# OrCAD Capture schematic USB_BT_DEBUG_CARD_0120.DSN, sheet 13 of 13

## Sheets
13 PAGE11 P5V to P3V3/ Super cap: size A3
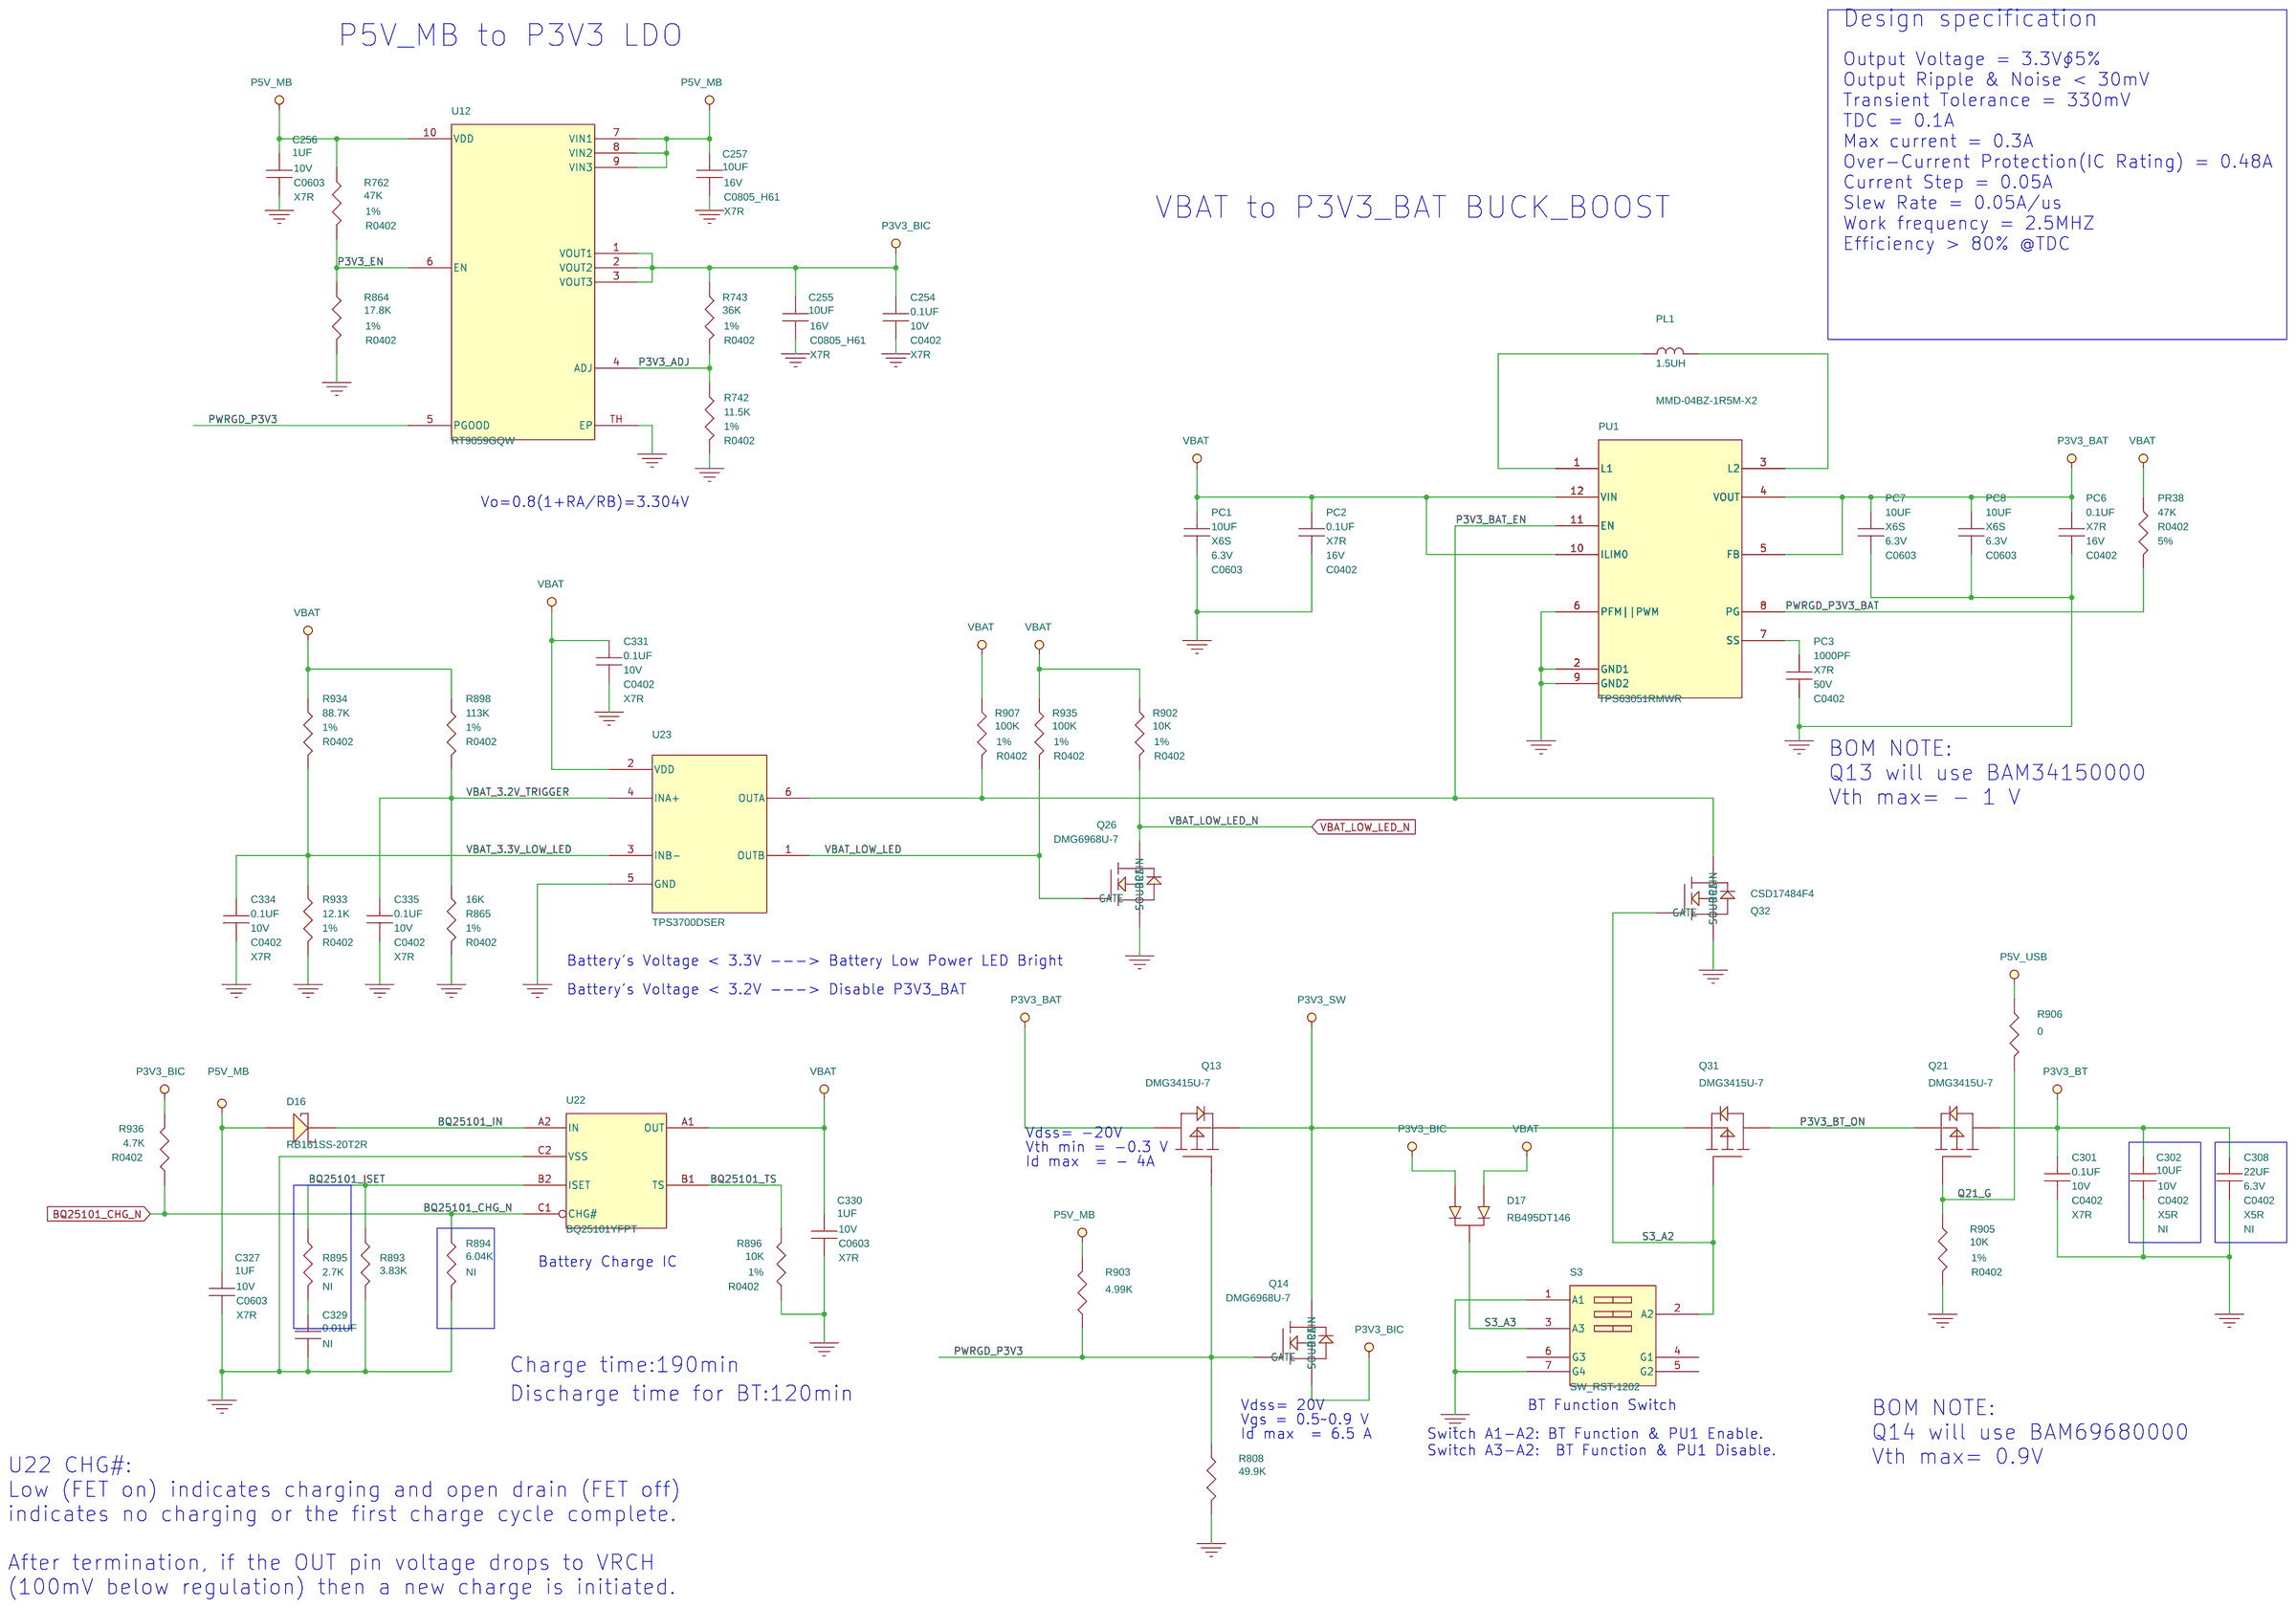
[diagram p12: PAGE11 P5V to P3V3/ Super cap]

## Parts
C254  0.1UF  [C0402]
C255  10UF  [C0805_H61]
C256  1UF  [C0603]
C257  10UF  [C0805_H61]
C301  0.1UF  [C0402]
C302  10UF  [C0402]
C308  22UF  [C0402]
C327  1UF  [C0603]
C329  0.01UF  [C0402]
C330  1UF  [C0603]
C331  0.1UF  [C0402]
C334  0.1UF  [C0402]
C335  0.1UF  [C0402]
D16  RB161SS-20T2R  [D0603_RB161SS-20T2R]
D17  RB495DT146  [SOT346_0-95_2-9X1-6]
PC1  10UF  [C0603]
PC2  0.1UF  [C0402]
PC3  1000PF  [C0402]
PC6  0.1UF  [C0402]
PC7  10UF  [C0603]
PC8  10UF  [C0603]
PL1  1.5UH  [L_MMD-04BZ-1R5M-X2]
PR38  47K  [R0402]
PU1  TPS63051RMWR  [VQFN12_0-5_2-5X2-5]
Q13  DMG3415U-7  [SOT23_GDSXC]
Q14  DMG6968U-7  [SOT23_GDSXC]
Q21  DMG3415U-7  [SOT23_GDSXC]
Q26  DMG6968U-7  [SOT23_GDSXC]
Q31  DMG3415U-7  [SOT23_GDSXC]
Q32  CSD17484F4  [PICOSTAR_GDS]
R742  11.5K  [R0402]
R743  36K  [R0402]
R762  47K  [R0402]
R808  49.9K  [R0402]
R864  17.8K  [R0402]
R865  16K  [R0402]
R893  3.83K  [R0402]
R894  6.04K  [R0402]
R895  2.7K  [R0402]
R896  10K  [R0402]
R898  113K  [R0402]
R902  10K  [R0402]
R903  4.99K  [R0402]
R905  10K  [R0402]
R906  0  [R0402]
R907  100K  [R0402]
R933  12.1K  [R0402]
R934  88.7K  [R0402]
R935  100K  [R0402]
R936  4.7K  [R0402]
S3  SW_RST-1202  [SW_RST-1202]
U12  RT9059GQW  [DFN10_THXE]
U22  BQ25101YFPT  [DSBGA6_0-4_0-88X1-58]
U23  TPS3700DSER  [WSON6_0-5_1-5X1-5]

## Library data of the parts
C254 C331 = CAP_NP: CAP CHIP 0.1U 10V(+-5%.X7R.0402); CLASS: DISCRETE; CMPLS_LVL: PF(V1)_Tmp; Data: WTC_LF_CAP SERIES-3.pdf; From_pj: TU2-ANNIE; Lifecycle: Comp-Approve; MATERIAL: X7R; Manuf_PN: 0402B104J100CT; Manuf_name: WALSIN TECHNOLOGY CORPORATION; Manuftr: WTC; Part_Type: *LF_C0402; Standard: ##; TOLERANCE: 5%; TOP_BOT: TOP; VOLTAGE: 10V; fp_ECN: 0402 SERIES_LL34.xls
C255 C257 = CAP_NP: CAP CHIP 10UF 16V(+-10%,X7R,0805); CLASS: DISCRETE; CMPLS_LVL: EP(V1); Data: SAM_MLCC SERIES_20130308.pdf; From_pj: T2H-CHEESE; Lifecycle: Comp-Approve; MATERIAL: X7R; Manuf_PN: CL21B106KOQNNNE; Manuf_name: SAMSUNG ELECTRONICS CO.,LTD; Manuftr: SAM; Part_Type: *LF_C0805; RD_CMPLS_LVL: EP(V1); TOLERANCE: 10%; TOP_BOT: TOP; VOLTAGE: 16V
C256 C327 C330 = CAP_NP: CAP CHIP 1U 10V(+-10%.X7R.0603); CLASS: DISCRETE; CMPLS_LVL: EP; Data: WTC_CAPACITOR SERIES.pdf; From_pj: T94-JEFF; Lifecycle: Comp-Approve; MATERIAL: X7R; Manuf_PN: 0603B105K100CT; Manuf_name: WALSIN TECHNOLOGY CORPORATION; Manuftr: WTC; Part_Type: *LF_C0603; Standard: ##; TOLERANCE: 10%; TOP_BOT: TOP; VOLTAGE: 10V
C301 C334 C335 = CAP_NP: CAP CHIP 0.1U 10V(+-5%.X7R.0402); CLASS: DISCRETE; CMPLS_LVL: PF(V1)_Tmp; Data: WTC_LF_CAP SERIES-3.pdf; From_pj: TU2-ANNIE; Lifecycle: Comp-Approve; MATERIAL: X7R; Manuf_PN: 0402B104J100CT; Manuf_name: WALSIN TECHNOLOGY CORPORATION; Manuftr: WTC; Part_Type: *LF_C0402; Standard: ##; TOLERANCE: 5%; TOP_BOT: BOT; VOLTAGE: 10V; fp_ECN: 0402 SERIES_LL34.xls
C302 = CAP_NP: CAP CHIP 10U 10V (+-20%, X5R, 0402); CLASS: DISCRETE; Data: CL05A106MP5NUNC.pdf; From_pj: T6VA-RAYMOND; Lifecycle: Comp-Approve; MATERIAL: X5R; Manuf_PN: CL05A106MP5NUNC; Manuf_name: SAMSUNG ELECTRONICS CO.,LTD (Samsung Mobile Display) / SAMSUNG SDI CO.,LTD; Manuftr: SAM; Not_insert: NI; Part_Type: *LF_C0402; RD_CMPLS_LVL: EP(V1); TOLERANCE: 20%; TOP_BOT: BOT; VOLTAGE: 10V; fp_ECN: 0402 SERIES_LL34.xls
C308 = CAP_NP: CAP CHIP 22U 6.3V(+-20%,X5R,0402); CLASS: DISCRETE; CMPLS_LVL: EP(V1); From_pj: T7A-JOSEPH; Lifecycle: Comp-Release Qty; MATERIAL: X5R; Manuf_PN: GRM155R60J226M; Manuf_name: MURATA ERIE N.A. INC TAIWAN BRANCH Okayama Murata Mfg.Co.,Ltd.Wakura Murata Mfg. Co., Ltd.; Manuftr: MUR; Not_insert: NI; Part_Category: Non-Consign; Part_Type: *LF_C0402; RD_CMPLS_LVL: EP(V1); TOLERANCE: 20%; TOP_BOT: BOT; VOLTAGE: 6.3V; fp_ECN: 0402 SERIES_LL34.xls
C329 = CAP_NP: CAP CHIP 0.01U 25V (+-5%,X7R,0402); CLASS: DISCRETE; CMPLS_LVL: EP(V1); Data: MUR_GRM155R71E103J.pdf; From_pj: T2H-WADE; Lifecycle: Comp-Approve; MATERIAL: X7R; Manuf_PN: GRM155R71E103J; Manuf_name: MURATA ERIE N.A. INC TAIWAN BRANCH Okayama Murata Mfg.Co.,; Manuftr: MUR; Not_insert: NI; Part_Type: *LF_C0402; RD_CMPLS_LVL: EP(V1); TOLERANCE: 5%; TOP_BOT: BOT; VOLTAGE: 25V; fp_ECN: 0402 SERIES_LL34.xls
D16 = MBRS340_0: DIODE SMD RB161SS-20T2R(30V,1A)SCHOTTKY; CLASS: IC; Data: ROH_RB161SS-20T2R.pdf; From_pj: F06-SHERRY; Lifecycle: Comp-Release Qty; MATERIAL: IC; Manuf_name: ROHM CO.,LTD.; Manuftr: ROH; Part_Type: *LF_Semiconductor; RD_CMPLS_LVL: EP(V1); TOP_BOT: TOP
D17 = RB495DT146: DIODE SMD RB495DT146(40V,0.4A); CLASS: IC; CMPLS_LVL: EU(V1); Data: ROH_RB495DT146.pdf; ESD_CDM: NA; ESD_HBM: NA; ESD_MM: NA; From_pj: S5H-HARRY; Lifecycle: Comp-Approve; MATERIAL: IC; MSD: NA; Manuf_name: ROHM CO.,LTD.; Manuftr: ROH; PIN_LENGTH_LONG_PIN: 0 MILS; PIN_LENGTH_SHORT_PIN: 0 MILS; Part_Type: *LF_Semiconductor; RD_CMPLS_LVL: EU(V1)
PC1 PC7 PC8 = CAP_NP: CAP CHIP 10U 6.3V(+-20%,X6S,0603); CLASS: DISCRETE; CMPLS_LVL: EP(V1); Data: MUR_JEMCG-4187DZ_20131126.pdf; From_pj: F06-RAYMOND; Lifecycle: Comp-Approve; MATERIAL: X6S; Manuf_PN: GRM188C80J106M; Manuf_name: MURATA ERIE N.A. INC TAIWAN BRANCH Okayama Murata Mfg.Co.,; Manufacturer: MAT; Manuftr: MUR; Part_Type: *LF_C0603; RD_CMPLS_LVL: EP(V1); TOLERANCE: 20%; TOP_BOT: TOP; VOLTAGE: 6.3V
PC2 PC6 = CAP_NP: CAP CHIP 0.1U 16V(10%.X7R.0402); CLASS: DISCRETE; CMPLS_LVL: EP; Data: MUR_LF_CAP SERIES_1.pdf; From_pj: S10-ANTONY; MATERIAL: X7R; Manuf_PN: GRM155R71C104K; Manuf_name: MURATA ERIE N.A. INC TAIWAN BRANCH Okayama Murata Mfg.Co..Ltd. Wakura Murata Mfg; Manufacturer: TAY; Manuftr: MUR; Part_Type: *LF_C0402; Standard: ##; Status: Preferred; TOLERANCE: 10%; TOP_BOT: TOP; VOLTAGE: 16V
PC3 = CAP_NP: CAP CHIP 1000P 50V(+-5%.X7R.0402); CLASS: DISCRETE; CMPLS_LVL: EP; Data: RHT_LF_CAP SERIES-2.pdf; From_pj: A05-DEMON; MATERIAL: X7R; Manuf_PN: C1005X7R102JGT; Manuf_name: ACER PERIPHERALS INC.(Darfon Electronics Corp.); Manufacturer: TAY; Manuftr: API; Part_Type: *LF_C0402; Status: Preferred; TOLERANCE: 5%; TOP_BOT: TOP; VOLTAGE: 50V; fp_ECN: 0402 SERIES_LL34.xls
PL1 = L: IND SMD 1.5UH 20% 4A MMD-04BZ-1R5M-X2; CLASS: DISCRETE; CMPLS_LVL: EP(V1); Current_Amp: 4A; Data: MAG_MMD-04BZ-1R5M-X2.pdf; From_pj: S2B-KC; Lifecycle: Comp-Approve; MATERIAL: IND; Manuf_PN: MMD-04BZ-1R5M-X2; Manuf_name: MAG. LAYERS (MAG.LAYERS Scientific-Technics Co., Ltd); Manuftr: MAG; Part_Type: *LF_Inductor; RD_CMPLS_LVL: EP(V1); TOP_BOT: TOP; fp_ECN: L_MMD-04BZ-1R5M-X2.msg
PR38 = R: RES CHIP 47K 1/16W +-5% (0402); CLASS: DISCRETE; CMPLS_LVL: EP; Data: WTC_LF_WR SERIES-4.pdf; From_pj: S93-MARTIN; Lifecycle: Comp-Approve; MATERIAL: CHIP; Manuf_PN: WR04X473 JTL; Manuf_name: WALSIN TECHNOLOGY CORPORATION; Manufacturer: CYN; Manuftr: WTC; Part_Type: *LF_Resistor; TOLERANCE: 5%; TOP_BOT: TOP; WATTAGE: 1/16W; fp_ECN: 0402 SERIES_LL34.xls
PU1 = TPS63051RMWR: IC OTHER(12P)TPS63051RMWR(VQFN-HR); CLASS: IC; Data: TIC_TPS63051RMWR_revJULY-2015.pdf; From_pj: F08-ANSON; Lifecycle: P/N Release; MATERIAL: IC; Manuf_name: TEXAS INSTRUMENTS SUPPLY CO.,; Manuftr: TIC; Part_Type: *LF_Chipset; RD_CMPLS_LVL: EP(V1); Standard: Potential; TOP_BOT: TOP
Q13 Q21 Q31 = MOSFET_PCH_GDS: TRANS MOS DMG3415U-7(-20V,-4A,0.9W)SOT23; CLASS: IC; CMPLS_LVL: EP(V1); Data: DDS_DMG3415U_REV3-2.pdf; From_pj: S1N-AI-JU; Lifecycle: Comp-Approve; MATERIAL: IC; Manuf_name: DIODES TAIWAN CO.,LTD.(Kai Hong Shanghai); Manuftr: DDS; Part_Type: *LF_Semiconductor; TOP_BOT: TOP
Q14 Q26 = MOSFET_N_GSD: TRANS MOS DMG6968U-7(20V,6.5A,1.3W)SOT23; CLASS: IC; Data: DDS_DMG6968U.pdf; From_pj: S1N-AI-JU; Lifecycle: Comp-Approve; MATERIAL: IC; Manuf_name: DIODES TAIWAN CO.,LTD.(Kai Hong Shanghai); Manuftr: DDS; Part_Type: *LF_Semiconductor; RD_CMPLS_LVL: EP(V1); TOP_BOT: TOP
Q32 = MOSFET_N_GSD: TRANS MOS CSD17484F4(30V,3A,0.5W); CLASS: IC; Data: TIC_CSD17484F4.pdf; ESD_CDM: NA; ESD_HBM: NA; ESD_MM: NA; From_pj: F08-TOM; Lifecycle: P/N Release; MATERIAL: IC; MSD: NA; Manuf_name: TEXAS INSTRUMENTS SUPPLY CO.,; Manuftr: TIC; PIN_LENGTH_LONG_PIN: 0 MILS; PIN_LENGTH_SHORT_PIN: 0 MILS; Part_Type: *LF_Semiconductor; RD_CMPLS_LVL: EP(V1); Standard: Potential; TOP_BOT: BOT
R742 = R: RES CHIP 11.5K 1/16W +-1%( 0402); CLASS: DISCRETE; CMPLS_LVL: EP; Data: MAT_LF_RES SERIES.pdf; From_pj: LSI-KC; Lifecycle: Comp-Approve; MATERIAL: CHIP; Manuf_PN: ERJ2RKF1152X; Manuf_name: MATSUSHITA ELECTRONICS CORPORATION (PANASONIC)Wuxi Matsushita Battery Co.. Ltd; Manuftr: MAT; Part_Type: *LF_Resistor; TOLERANCE: 1%; TOP_BOT: TOP; WATTAGE: 1/16W; fp_ECN: 0402 SERIES_LL34.xls
R743 = R: RES CHIP 36K 1/16W +-1%(0402); CLASS: DISCRETE; CMPLS_LVL: EP; Data: RHT_LF_RES SERIES-2.pdf; From_pj: LB6-JAMES; MATERIAL: CHIP; Manuf_PN: CR0236K0F002S; Manuf_name: RTECH TECHNOLOGY CO..LTD. (Compostar); Manuftr: RHT; Part_Type: *LF_Resistor; TOLERANCE: 1%; TOP_BOT: TOP; WATTAGE: 1/16W; fp_ECN: 0402 SERIES_LL34.xls
R762 = R: RES CHIP 47K 1/16W +-1% (0402); CLASS: DISCRETE; CMPLS_LVL: EP; Data: RHT_LF_RES SERIES-2.pdf; From_pj: T96-KC; Lifecycle: Comp-Release Qty; MATERIAL: CHIP; Manuf_PN: CR0247K0F002S; Manuf_name: RTECH TECHNOLOGY CO..LTD.(Compostar); Manuftr: RHT; Part_Type: *LF_Resistor; Standard: ##; TOLERANCE: 1%; TOP_BOT: TOP; WATTAGE: 1/16W; fp_ECN: 0402 SERIES_LL34.xls
R808 = R: RES CHIP 49.9K 1/16W +-1%(0402); CLASS: DISCRETE; CMPLS_LVL: EP; Data: WTC_LF_WR SERIES-4.pdf; From_pj: LU1-EASON; Lifecycle: Comp-Approve; MATERIAL: CHIP; Manuf_PN: WR04X4992FTL; Manuf_name: WALSIN TECHNOLOGY CORPORATION; Manuftr: WTC; Part_Type: *LF_Resistor; Standard: ##; TOLERANCE: 1%; TOP_BOT: TOP; WATTAGE: 1/16W; fp_ECN: 0402 SERIES_LL34.xls
R864 = R: RES CHIP 17.8K 1/16W +- 1% (0402); CLASS: DISCRETE; CMPLS_LVL: EP; Data: WTC_LF_WR SERIES-4.pdf; From_pj: T96-KC; Lifecycle: Comp-Approve; MATERIAL: CHIP; Manuf_PN: WR04X1782FTL; Manuf_name: WALSIN TECHNOLOGY CORPORATION; Manuftr: WTC; Part_Type: *LF_Resistor; Standard: ##; TOLERANCE: 1%; TOP_BOT: TOP; WATTAGE: 1/16W; fp_ECN: 0402 SERIES_LL34.xls
R865 = R: RES CHIP 16K 1/16W +-1%(0402); CLASS: DISCRETE; CMPLS_LVL: EP; Data: YGO_RC SERIES_1.pdf; From_pj: TU1-RICHARD; MATERIAL: CHIP; Manuf_PN: RC0402FR-0716KL; Manuf_name: YAGEO CORPORATION; Manuftr: YGO; Part_Type: *LF_Resistor; TOLERANCE: 1%; TOP_BOT: TOP; WATTAGE: 1/16W; fp_ECN: 0402 SERIES_LL34.xls
R893 = R: RES CHIP 3.83K 1/16W +-1%(0402); CLASS: DISCRETE; CMPLS_LVL: EP(V1); Data: WTC_LF_WR SERIES-5.pdf; From_pj: S81K-KEN; Lifecycle: Comp-Approve; MATERIAL: CHIP; Manuf_PN: WR04X3831FTL; Manuf_name: WALSIN TECHNOLOGY CORPORATION; Manuftr: WTC; Part_Type: *LF_Resistor; RD_CMPLS_LVL: EP(V1); TOLERANCE: 1%; TOP_BOT: BOT; WATTAGE: 1/16W; fp_ECN: 0402 SERIES_LL34.xls
R894 = R: RES CHIP 6.04K 1/16W +-1%(0402); CLASS: DISCRETE; CMPLS_LVL: EP; Data: YGO_RC0201.pdf; From_pj: YK1-KEVIN; Lifecycle: Comp-Approve; MATERIAL: CHIP; Manuf_PN: RC0402FR-076K04; Manuf_name: YAGEO CORPORATION; Manuftr: YGO; Not_insert: NI; Part_Type: *LF_Resistor; Standard: ##; TOLERANCE: 1%; TOP_BOT: BOT; WATTAGE: 1/16W; fp_ECN: 0402 SERIES_LL34.xls
R895 = R: RES CHIP 2.7K 1/16W +-1%(0402); CLASS: DISCRETE; CMPLS_LVL: EP; Data: RHT_LF_RES SERIES-2.pdf; From_pj: S93-MARTIN; Lifecycle: Comp-Approve; MATERIAL: CHIP; Manuf_PN: CR022K70F002S; Manuf_name: RTECH TECHNOLOGY CO..LTD. (Compostar); Manuftr: RHT; Not_insert: NI; Part_Type: *LF_Resistor; TOLERANCE: 1%; TOP_BOT: BOT; WATTAGE: 1/16W; fp_ECN: 0402 SERIES_LL34.xls
R896 R902 R905 = R: RES CHIP 10K 1/16W +-1% (0402); CLASS: DISCRETE; CMPLS_LVL: EP; Data: WTC_LF_WR SERIES.pdf; From_pj: S82; Lifecycle: Comp-Approve; MATERIAL: CHIP; Manuf_PN: RR0510S-103-FN; Manuf_name: CYNTEC CO.. LTD.; Manuftr: CYN; Part_Type: *LF_Resistor; Status: Preferred; TOLERANCE: 1%; TOP_BOT: TOP; WATTAGE: 1/16W; fp_ECN: 0402 SERIES_LL34.xls
R898 = R: RES CHIP 113K 1/16W +-1%(0402); CLASS: DISCRETE; CMPLS_LVL: EP(V1); From_pj: T6MQ-TERRY; Lifecycle: Comp-Release Qty; MATERIAL: CHIP; Manuf_PN: RR0510S-1133-FN; Manuf_name: CYNTEC CO., LTD.; Manuftr: CYN; Part_Type: *LF_Resistor; RD_CMPLS_LVL: EP(V1); TOLERANCE: 1%; TOP_BOT: TOP; WATTAGE: 1/16W; fp_ECN: 0402 SERIES_LL34.xls
R903 = R: RES CHIP 4.99K 1/16W +-1% (0402); CLASS: DISCRETE; Data: YAGEO_RC.pdf; From_pj: S82-ICE; MATERIAL: CHIP; Manuf_PN: RC0402FR-074K99; Manuf_name: YAGEO CORPORATION; Manuftr: YGO; Part_Type: Resistor; Status: Normal; TOLERANCE: 1%; TOP_BOT: TOP; WATTAGE: 1/16W; fp_ECN: 0402 SERIES_LL34.xls
R906 = R: RESISTOR CHIP 0 1/16W +-5%(0402); CLASS: DISCRETE; CMPLS_LVL: EP; Data: WTC_LF_WR SERIES.pdf; Lifecycle: Comp-Approve; MATERIAL: CHIP; Manuf_PN: RR0510X-000-XN; Manuf_name: CYNTEC CO.. LTD.; Manuftr: CYN; Part_Type: *LF_Resistor; Status: Preferred; TOLERANCE: 5%; TOP_BOT: BOT; WATTAGE: 1/16W; fp_ECN: 0402 SERIES_LL34.xls
R907 R935 = R: RES CHIP 100K 1/16W +-1%(0402)EF; CLASS: DISCRETE; From_pj: S6E-KENHU; Lifecycle: Comp-Approve; MATERIAL: CHIP; Manuf_PN: WR04X1003FTR; Manuf_name: WALSIN TECHNOLOGY CORPORATION; Manuftr: WTC; Part_Type: *LF_Resistor; RD_CMPLS_LVL: EP(V1); Standard: End of Design; TOLERANCE: 1%; TOP_BOT: TOP; WATTAGE: 1/16W; fp_ECN: 0402 SERIES_LL34.xls
R933 = R: RES CHIP 12.1K 1/16W +-1%(0402); CLASS: DISCRETE; CMPLS_LVL: EP; Data: WTC_LF_WR SERIES-4.pdf; From_pj: T96-KC; MATERIAL: CHIP; Manuf_PN: WR04X1212FTL; Manuf_name: WALSIN TECHNOLOGY CORPORATION; Manuftr: WTC; Part_Type: *LF_Resistor; TOLERANCE: 1%; TOP_BOT: BOT; WATTAGE: 1/16W; fp_ECN: 0402 SERIES_LL34.xls
R934 = R: RES CHIP 88.7K 1/16W +-1%(0402); CLASS: DISCRETE; Data: YGO_RC SERIES_1.pdf; From_pj: LB9-ERIC; Lifecycle: Comp-Approve; MATERIAL: CHIP; Manuf_PN: RC0402FR-0788K7L; Manuf_name: YAGEO CORPORATION; Manuftr: YGO; Part_Type: *LF_Resistor; RD_CMPLS_LVL: EP(V1); TOLERANCE: 1%; TOP_BOT: BOT; WATTAGE: 1/16W; fp_ECN: 0402 SERIES_LL34.xls
R936 = R: RES CHIP 4.7K 1/16W +-5% (0402); CLASS: DISCRETE; CMPLS_LVL: EP; Data: WTC_LF_WR SERIES.pdf; Lifecycle: Comp-Approve; MATERIAL: CHIP; Manuf_PN: RR0510S-472-JN; Manuf_name: CYNTEC CO.. LTD.; Manuftr: CYN; Part_Type: *LF_Resistor; Status: Preferred; TOLERANCE: 5%; TOP_BOT: BOT; WATTAGE: 1/16W; fp_ECN: 0402 SERIES_LL34.xls
S3 = RST-1202: SWITCH SLIDE SMD 3P RST-1202; CLASS: IO; CMPLS_LVL: EP(V1)_Tmp; Data: RST-1202.pdf; From_pj: LU1-EASON; Lifecycle: Comp-Approve; MATERIAL: MECH; Manuf_name: TOKAI SANGYO CO..LTD; Manuftr: TKS; Part_Type: *LF_Mech; Standard: Non-Preferred; TOP_BOT: TOP
U12 = RT9059GQW: IC OTHER(10P) RT9059GQW(WDFN); CLASS: IC; Data: RTK_RT9059_rev2012.pdf; From_pj: S4E-ALAN; Lifecycle: Comp-Approve; MATERIAL: IC; Manuf_name: RICHTEK TECHNOLOGY CORPORATION; Manuftr: RTK; Part_Type: *LF_Chipset; RD_CMPLS_LVL: EP(V1); TOP_BOT: TOP
U22 = BQ25101YFPT: IC CTRL(6P)BQ25101YFPT(DSBGA); CLASS: IC; CMPLS_LVL: EU(V1); Data: TIC_BQ25101YFPT.pdf; From_pj: F08-MIKE; Lifecycle: P/N Release; MATERIAL: IC; Manuf_name: TEXAS INSTRUMENTS SUPPLY CO.,; Manuftr: TIC; Part_Type: *LF_Chipset; RD_CMPLS_LVL: EU(V1); Standard: Potential; TOP_BOT: TOP
U23 = TPS3700DSER: IC OTHER(6P)TPS3700DSER(WSON); CLASS: IC; Data: TIC_TPS3700.pdf; From_pj: T2H-GAVEN; Lifecycle: Comp-Approve; MATERIAL: IC; Manuf_name: TEXAS INSTRUMENTS SUPPLY CO.,; Manuftr: TIC; Part_Type: *LF_Chipset; RD_CMPLS_LVL: EP(V1); Standard: Potential; TOP_BOT: TOP

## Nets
GND: C254.2 C255.2 C256.2 C257.2 C301.2 C302.2 C308.2 C327.2 C329.2 C330.2 C331.2 C334.2 C335.2 PC1.2 PC2.2 PC3.2 PC6.2 PC7.2 PC8.2 PU1.2(GND1) PU1.6(PFM||PWM) PU1.9(GND2) Q26.S(SOURCE) Q32.S(SOURCE) R742.2 R808.2 R864.2 R865.2 R893.2 R894.2 R896.2 R905.2 R933.2 S3.1(A1) S3.7(G4) U12.TH(EP) U22.C2(VSS) U23.5(GND) ; also on sheet 7 8 9 10 12
P3V3_ADJ: R742.1 R743.2 U12.4(ADJ)
P3V3_BAT: PC6.1 PC7.1 PC8.1 PU1.4(VOUT) PU1.5(FB) Q13.D
P3V3_BAT_EN: PU1.11(EN) Q32.D(DRAIN) R907.2 U23.6(OUTA)
P3V3_BIC: C254.1 C255.1 D17.2 Q14.S(SOURCE) R743.1 R936.1 U12.1(VOUT1) U12.2(VOUT2) U12.3(VOUT3) ; also on sheet 7 8 9 10 12
P3V3_BT: C301.1 C302.1 C308.1 Q21.D ; also on sheet 12
P3V3_BT_ON: Q21.S Q31.D
P3V3_EN: R762.2 R864.1 U12.6(EN)
P3V3_SW: Q13.S Q14.D(DRAIN) Q31.S ; also on sheet 12
P5V_MB: C256.1 C257.1 C327.1 D16.A R762.1 R903.2 U12.7(VIN1) U12.8(VIN2) U12.9(VIN3) U12.10(VDD) ; also on sheet 7 8 9 12
P5V_USB: R906.2 ; also on sheet 12
VBAT: C330.1 C331.1 D17.1 PC1.1 PC2.1 PR38.1 PU1.10(ILIM0) PU1.12(VIN) R898.1 R902.1 R907.1 R934.1 R935.1 U22.A1(OUT) U23.2(VDD) ; also on sheet 8 9
VBAT_3.2V_TRIGGER: C335.1 R865.1 R898.2 U23.4(INA+)
VBAT_3.3V_LOW_LED: C334.1 R933.1 R934.2 U23.3(INB-)
VBAT_LOW_LED: Q26.G(GATE) R935.2 U23.1(OUTB)
VBAT_LOW_LED_N: Q26.D(DRAIN) R902.2 ; also on sheet 9
BQ25101_CHG_N: R894.1 R936.2 U22.C1(CHG#) ; also on sheet 9
BQ25101_IN: D16.C U22.A2(IN)
BQ25101_ISET: R893.1 R895.1 U22.B2(ISET)
BQ25101_TS: R896.1 U22.B1(TS)
G1: S3.4(G1)
G2: S3.5(G2)
G3: S3.6(G3)
PWRGD_P3V3: Q13.G Q14.G(GATE) R808.1 R903.1 U12.5(PGOOD)
PWRGD_P3V3_BAT: PR38.2 PU1.8(PG)
Q21_G: Q21.G R905.1 R906.1
S3_A2: Q31.G Q32.G(GATE) S3.2(A2)
S3_A3: D17.3 S3.3(A3)
N18364020: PL1.1 PU1.1(L1)
N18364026: PL1.2 PU1.3(L2)
N18364174: PC3.1 PU1.7(SS)
N18393594: C329.1 R895.2

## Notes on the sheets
sheet 13
- Design specification
- P5V_MB to P3V3 LDO
- Output Voltage = 3.3V∮5%
  Output Ripple & Noise < 30mV
  Transient Tolerance = 330mV
  TDC = 0.1A
  Max current = 0.3A
  Over-Current Protection(IC Rating) = 0.48A
  Current Step = 0.05A
  Slew Rate = 0.05A/us
  Work frequency = 2.5MHZ
  Efficiency > 80% @TDC
- VBAT to P3V3_BAT BUCK_BOOST
- Vo=0.8(1+RA/RB)=3.304V
- BOM NOTE:
  Q13 will use BAM34150000
  Vth max= - 1 V
- Battery's Voltage < 3.3V ---> Battery Low Power LED Bright
- Battery's Voltage < 3.2V ---> Disable P3V3_BAT
- Vdss= -20V
- Vth min = -0.3 V
- Id max  = - 4A
- Battery Charge IC
- Charge time:190min
- Discharge time for BT:120min
- Vdss= 20V
- BT Function Switch
- BOM NOTE:
  Q14 will use BAM69680000
  Vth max= 0.9V
- Vgs = 0.5~0.9 V
- Id max  = 6.5 A
- Switch A1-A2: BT Function & PU1 Enable.
  Switch A3-A2:  BT Function & PU1 Disable.
- U22 CHG#:
  Low (FET on) indicates charging and open drain (FET off)
  indicates no charging or the first charge cycle complete.
  After termination, if the OUT pin voltage drops to VRCH
  (100mV below regulation) then a new charge is initiated.
